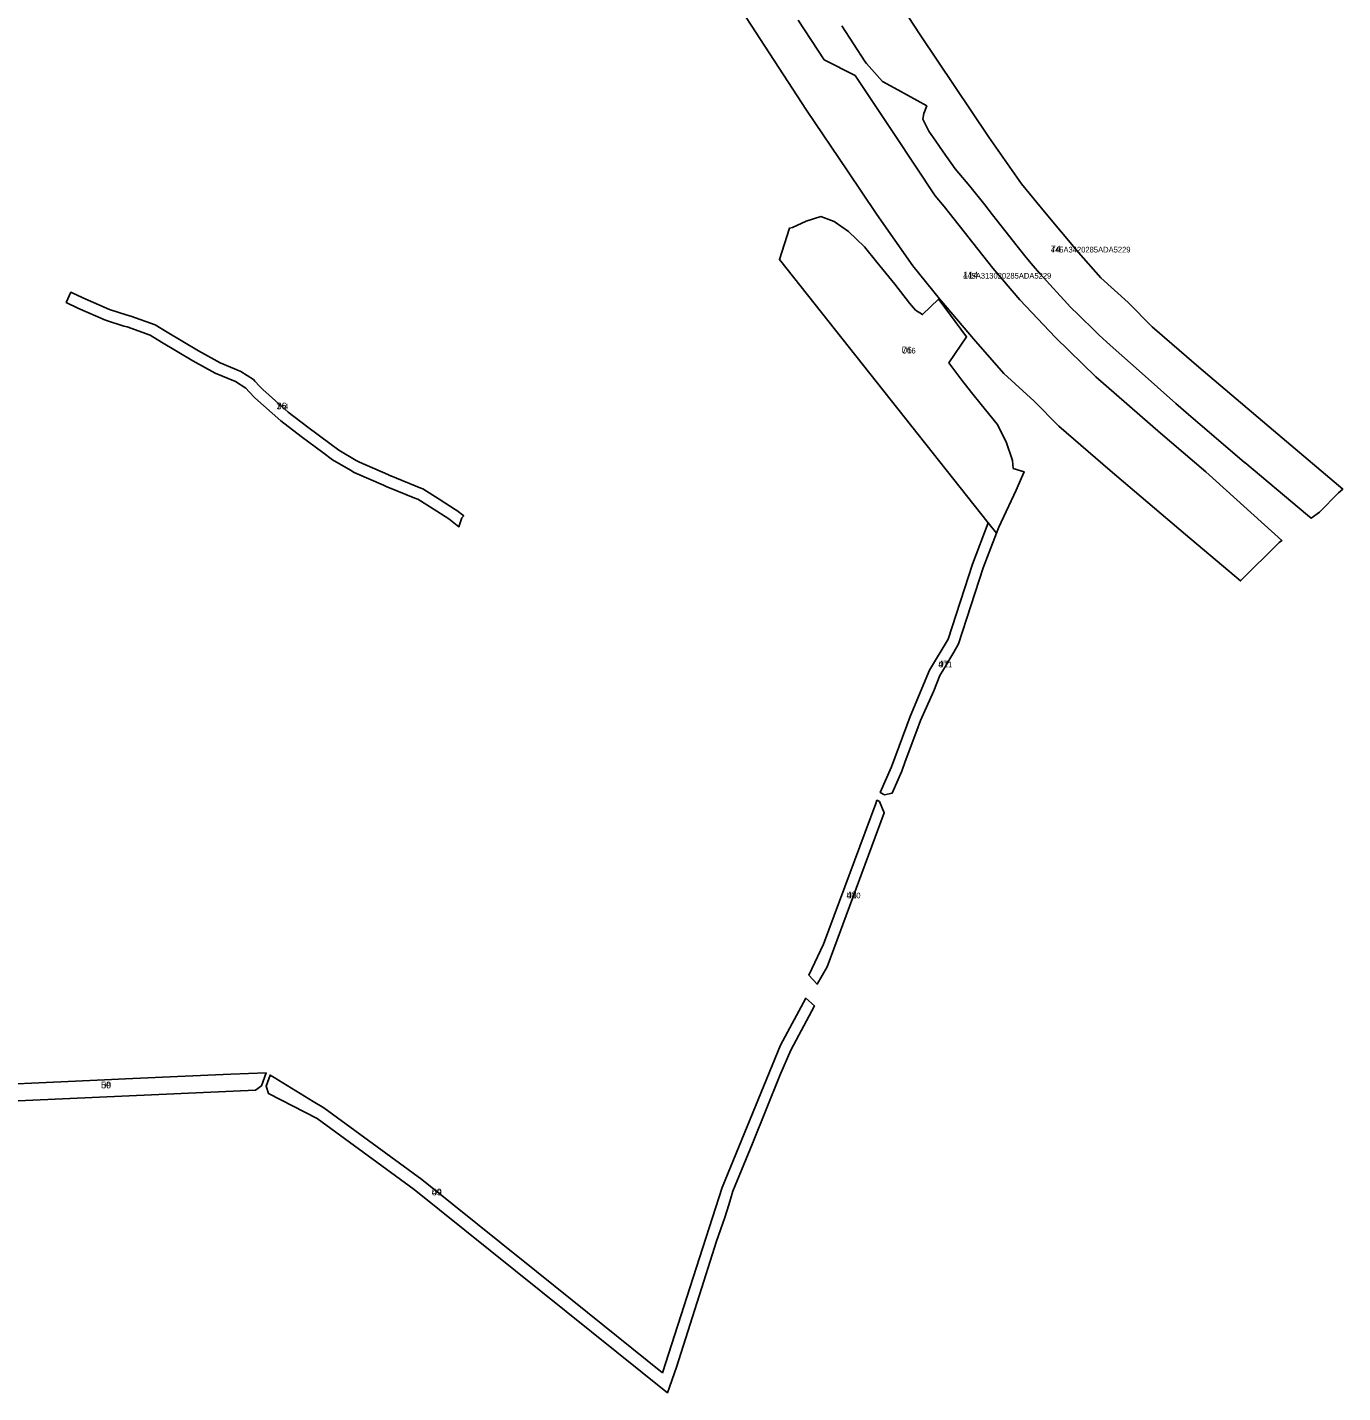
# Model space of a CAD drawing. Extents: x -545623 to -541713, y -1153152 to -1149975.
# Drawn here: x -544231 to -543071, y -1152535 to -1151332 of the extents above; entities that cross this region are included whole.
import ezdxf

# ---------------------------------------------------------------- set-up
doc = ezdxf.new("R2010")
doc.units = 0
for name, color, linetype in [('96120023', 7, 'Continuous'), ('96140023', 7, 'Continuous'), ('ID_VPO', 7, 'Continuous'), ('ID_VPS', 7, 'Continuous')]:
    doc.layers.add(name, color=color, linetype=linetype)

msp = doc.modelspace()

# ---------------------------------------------------------------- linework, layer by layer
at = {"layer": '96120023'}
for points in [[(-543500.7, -1151251.3), (-543444, -1151338.3), (-543383.2, -1151428.6), (-543354.4, -1151469.6), (-543334.3, -1151494.3), (-543304.3, -1151530), (-543284.5, -1151552.5), (-543260.5, -1151574.3), (-543239.5, -1151595.5), (-543198.2, -1151631.1), (-543132.5, -1151687), (-543071.4, -1151738.6), (-543075, -1151742), (-543091.9, -1151758.9), (-543099.2, -1151764.4), (-543102.4, -1151761.7), (-543102.6, -1151761.5), (-543157.6, -1151715.3), (-543157.9, -1151715.1), (-543168.6, -1151706), (-543195.1, -1151683.4), (-543207.4, -1151673), (-543218.4, -1151663.2), (-543250.7, -1151634.5), (-543273.8, -1151614.1), (-543279.6, -1151608.9), (-543286.2, -1151602.9), (-543289.4, -1151599.7), (-543304.2, -1151585.2), (-543311.3, -1151578.3), (-543316.9, -1151572.2), (-543320.5, -1151568.2), (-543338.6, -1151548.4), (-543344.4, -1151542), (-543350.4, -1151534.5), (-543358.3, -1151524.5), (-543380.2, -1151496.8), (-543387, -1151488.2), (-543400.2, -1151471.6), (-543413, -1151456.3), (-543423.6, -1151441.3), (-543430, -1151432.1), (-543436.3, -1151423.2), (-543441.6, -1151412.5), (-543440.5, -1151407.6), (-543438, -1151401), (-543463.5, -1151386.8), (-543477, -1151379.3), (-543491.1, -1151363.6), (-543492.4, -1151362.2), (-543513, -1151330.5)], [(-543551.5, -1151325.3), (-543528.4, -1151360.2), (-543501.2, -1151374.2), (-543466, -1151427), (-543430.6, -1151480.1), (-543422.6, -1151489.6), (-543379.7, -1151544), (-543356, -1151571.7), (-543324.6, -1151605.1), (-543288.9, -1151639.8), (-543232.1, -1151689.3), (-543192.1, -1151723.4), (-543125, -1151783.9), (-543127.3, -1151785.6), (-543161.5, -1151819.6), (-543210.1, -1151778.6), (-543276.3, -1151722.2), (-543321.5, -1151683.3), (-543343.5, -1151661), (-543370.1, -1151636.9), (-543395.2, -1151608.3), (-543426.8, -1151570.9), (-543450.2, -1151542), (-543482.1, -1151496.5), (-543507.9, -1151458.2), (-543544, -1151404.6), (-543601.1, -1151317.1)]]:
    msp.add_lwpolyline(points, dxfattribs=at)
msp.add_lwpolyline([(-544035.3, -1151652.8), (-544038.1, -1151649.7), (-544047.3, -1151643.9), (-544065.3, -1151636.4), (-544085, -1151625.5), (-544112.6, -1151609), (-544122.6, -1151603), (-544142.9, -1151595.7), (-544145.7, -1151594.9), (-544162, -1151589.8), (-544186.2, -1151579.1), (-544196.6, -1151574.1), (-544192.4, -1151565.1), (-544182, -1151570), (-544158.5, -1151580.4), (-544142.7, -1151585.3), (-544139.7, -1151586.2), (-544118.3, -1151593.9), (-544107.5, -1151600.4), (-544080, -1151616.8), (-544060.9, -1151627.4), (-544042.7, -1151635), (-544031.6, -1151642), (-544030.3, -1151643.5), (-544026.2, -1151647.9), (-544023.4, -1151651), (-544001, -1151670.8), (-543983.5, -1151684.2), (-543964.3, -1151698.5), (-543956.3, -1151704.4), (-543941, -1151713.3), (-543938.1, -1151714.9), (-543913, -1151725.9), (-543910.7, -1151726.9), (-543910.5, -1151727), (-543883.9, -1151737.8), (-543882.1, -1151738.5), (-543867.8, -1151747.6), (-543853.6, -1151756.6), (-543852.4, -1151757.6), (-543846.2, -1151762.3), (-543847.8, -1151764), (-543850.4, -1151771.8), (-543859.4, -1151764.9), (-543873.2, -1151756.1), (-543886.7, -1151747.5), (-543887.7, -1151747.1), (-543914.5, -1151736.2), (-543917, -1151735.1), (-543942.7, -1151723.9), (-543946, -1151721.9), (-543961.8, -1151712.8), (-543970.3, -1151706.5), (-543989.5, -1151692.2), (-544007.3, -1151678.5), (-544030.4, -1151658.1)], close=True, dxfattribs=at)
at = {"layer": '96140023'}
for points in [[(-543361.8, -1151720.5), (-543352.3, -1151723.4), (-543354.6, -1151728.8), (-543359.2, -1151739.5), (-543374.5, -1151772.1), (-543376.6, -1151777.5), (-543383.8, -1151768.4), (-543567.9, -1151536.2), (-543559.1, -1151508.7), (-543556.4, -1151508.2), (-543544.3, -1151502.4), (-543531.3, -1151498.4), (-543524.4, -1151500.9), (-543519.6, -1151502.7), (-543507, -1151511.6), (-543492.9, -1151525.1), (-543482.2, -1151538.5), (-543466.3, -1151558), (-543453.3, -1151574.8), (-543448, -1151580.8), (-543441.7, -1151584.8), (-543427.6, -1151571.2), (-543427.2, -1151571.8), (-543402.9, -1151604.4), (-543418.5, -1151627.3), (-543407, -1151642.5), (-543398.6, -1151653.5), (-543390.1, -1151664.1), (-543376, -1151681.3), (-543368, -1151697), (-543362.6, -1151713.5)], [(-543435.5, -1151898.2), (-543419.1, -1151870.9), (-543397.7, -1151804.8), (-543383.8, -1151768.4), (-543376.6, -1151777.5), (-543383.1, -1151794.1), (-543388.2, -1151808.1), (-543410, -1151875), (-543414.3, -1151882.4), (-543417.8, -1151888.3), (-543420.1, -1151892.3), (-543426.6, -1151902.8), (-543431.9, -1151916.4), (-543443.5, -1151942.7), (-543446.8, -1151951.5), (-543457, -1151978.7), (-543459.9, -1151987.3), (-543465.5, -1152000), (-543468.4, -1152006.5), (-543475.3, -1152008), (-543479.1, -1152006), (-543469.2, -1151983.5), (-543452.8, -1151939)], [(-543529.1, -1152139.8), (-543483, -1152015.6), (-543482, -1152012.9), (-543479.8, -1152014), (-543475.5, -1152024), (-543519.9, -1152143.7), (-543525.8, -1152159.7), (-543534.7, -1152175), (-543541.9, -1152166.9)], [(-543778.2, -1152445.4), (-543889.8, -1152355.8), (-543975.4, -1152293.3), (-544018.4, -1152271.3), (-544020.3, -1152264.8), (-544016.9, -1152255.1), (-544013.4, -1152257.2), (-543978.8, -1152278.3), (-543969.6, -1152283.9), (-543883.1, -1152347), (-543856.5, -1152368.4), (-543813.2, -1152403.2), (-543782, -1152428.2), (-543750.6, -1152453.5), (-543671, -1152517.4), (-543644, -1152433.5), (-543618.4, -1152354), (-543567, -1152228.7), (-543544.7, -1152187.3), (-543537, -1152194), (-543557.9, -1152233), (-543567.6, -1152255.5), (-543591.7, -1152315.3), (-543609, -1152357.4), (-543611.1, -1152364.4), (-543612.6, -1152369.3), (-543616.1, -1152380.7), (-543623.5, -1152401.4), (-543634.5, -1152436.6), (-543658.5, -1152512.4), (-543666.6, -1152535)], [(-544167.1, -1152274.5), (-544167.1, -1152274.5), (-544304.4, -1152280.6), (-544304.3, -1152265.6), (-544162.8, -1152259.3), (-544144.4, -1152258.5), (-544098.5, -1152256.4), (-544051.4, -1152254.4), (-544020.4, -1152253), (-544024.4, -1152264.5), (-544029.7, -1152268.4)]]:
    msp.add_lwpolyline(points, close=True, dxfattribs=at)

# ---------------------------------------------------------------- texts
at = {"layer": '96120023'}
for s, rotation, p in [('445A3420285ADA5229', 0, (-543328.7, -1151530.1)), ('445A313020285ADA5229', 360, (-543406, -1151553.1)), ('T*4', 0, (-544011.2, -1151668.4))]:
    msp.add_text(s, height=5, rotation=rotation, dxfattribs=at).set_placement(p)
at = {"layer": '96140023'}
for s, rotation, p in [('U16', 360, (-543460.1, -1151619.1)), ('U11', 360, (-543427.9, -1151895.7)), ('U10', 360, (-543508.7, -1152099.3)), ('U8', 0, (-544165.9, -1152266.8)), ('U9', 0, (-543874.4, -1152361.1))]:
    msp.add_text(s, height=5, rotation=rotation, dxfattribs=at).set_placement(p)
at = {"layer": 'ID_VPO'}
for s, rotation, p in [('76', 360, (-543460.1, -1151619.1)), ('47', 360, (-543427.9, -1151895.7)), ('48', 360, (-543508.7, -1152099.3)), ('50', 0, (-544165.9, -1152266.8)), ('49', 0, (-543874.4, -1152361.1))]:
    msp.add_text(s, height=6, rotation=rotation, dxfattribs=at).set_placement(p)
at = {"layer": 'ID_VPS'}
for s, p in [('74', (-543328.7, -1151530.1)), ('114', (-543406, -1151553.1)), ('36', (-544011.2, -1151668.4))]:
    msp.add_text(s, height=6, rotation=0, dxfattribs=at).set_placement(p)

doc.saveas('drawing.dxf')
